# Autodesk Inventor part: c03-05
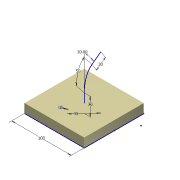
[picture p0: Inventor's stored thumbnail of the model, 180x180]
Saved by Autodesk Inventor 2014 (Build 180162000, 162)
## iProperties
Created: 2011-11
Part Number: c03-05
Material: Iron, Cast
Document SubType Name: Modeling
Designer: Thom Tremblay
Density: 7.25 g/cm^3
Mass: 1087.5 g
Surface Area: 260 cm^2
Volume: 150 cm^3
Appearance: Nylon 6
Author: Thom Tremblay
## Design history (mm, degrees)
sketch "Sketch1"
  geometry: L1 (50, -50)-(-50, -50); L2 (-50, -50)-(-50, 50); L3 (-50, 50)-(50, 50); L4 (50, 50)-(50, -50); C1 r 20 at (0, 0); C2 r 30 at (0, 0); 3 further points
  constraints: 8 end point, 2 centre point, 2 coincident, 2 midpoint, 2 parallel, 2 perpendicular, 1 horizontal, 1 horizontal alignment, 1 vertical alignment
  dimensions: "d0" = 100 distance of L2.end L3.end; "d3" = 40 diameter of C1; "d4" = 10 radial gap between concentric circles of C2 C1
extrude "Extrusion1" new body sketch "Sketch1" distance "d1" = 15; taper "d2" = 0 deg
sketch "Sketch2"
  geometry: L1 (0, 0)-(0, 30); L2 (12.794, 77.746)-(27.794, 103.727); A1 r 95.493 centre (95.493, 30) between (12.794, 77.746) and (0, 30)
  constraints: 4 end point, 2 point on circle, 2 tangent, 1 centre point, 1 vertical
  dimensions: "d5" = 30 distance of L1.start L1.end; "d7" = 50 dimension on A1; "d9" = 30 distance of L2.start L2.end; "d10" = 30 deg angle of L2 L1
body "Solid1"
